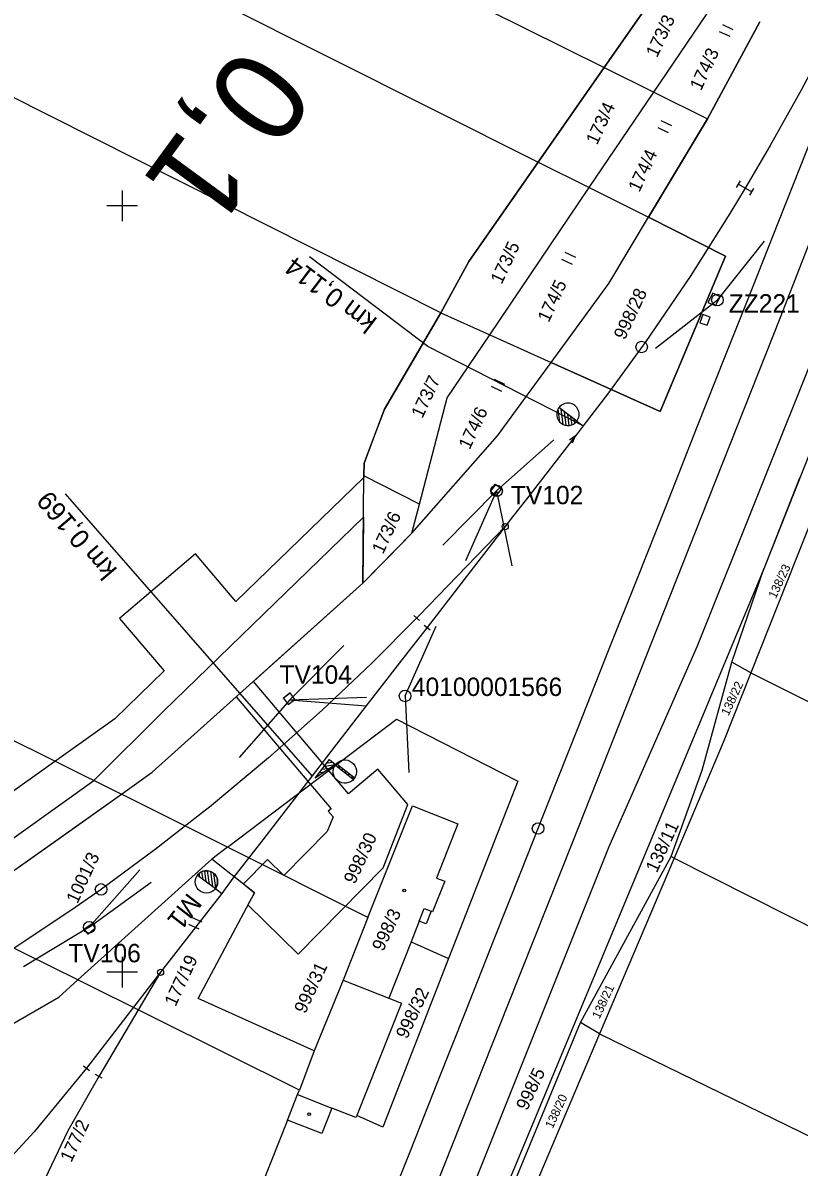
# Model space of a CAD drawing. Extents: x -755344 to -754412, y -1162670 to -1161477.
# Drawn here: x -754912.9 to -754811.6, y -1162225.4 to -1162076.1 of the extents above; entities that cross this region are included whole.
import ezdxf

# ---------------------------------------------------------------- set-up
doc = ezdxf.new("R2010")
doc.units = 0
for name, color, linetype in [('Body ŽBP', 7, 'Continuous'), ('hranice obvodu stavby', 7, 'Continuous'), ('Katastrální hranice', 7, 'Continuous'), ('Staniceni a namezniky', 7, 'Continuous'), ('Síť', 7, 'Continuous'), ('TZ_ostatní', 7, 'Continuous'), ('Vrstva 1', 7, 'Continuous'), ('Vrstva 12', 7, 'Continuous'), ('Vrstva 2', 7, 'Continuous'), ('Vrstva 3', 7, 'Continuous'), ('Vrstva 53', 7, 'Continuous'), ('Vrstva 55', 7, 'Continuous'), ('Vrstva 56', 7, 'Continuous'), ('Vrstva 57', 7, 'Continuous'), ('Vrstva 58', 7, 'Continuous'), ('Vrstva 59', 7, 'Continuous')]:
    doc.layers.add(name, color=color, linetype=linetype)

msp = doc.modelspace()

# ---------------------------------------------------------------- linework, layer by layer
at = {"layer": 'Body ŽBP'}
for p, q in [((-754822.28, -1162112.28), (-754816.13, -1162104.6)), ((-754822.28, -1162112.28), (-754830.36, -1162118.62)), ((-754822.9, -1162111.96), (-754822.9, -1162111.96)), ((-754822.26, -1162112.23), (-754822.3, -1162112.32)), ((-754822.28, -1162112.28), (-754822.28, -1162112.28)), ((-754851.1, -1162137.17), (-754843.64, -1162130.5)), ((-754851.1, -1162137.17), (-754858.13, -1162144.28)), ((-754851.1, -1162137.17), (-754855.18, -1162146.3)), ((-754851.08, -1162137.12), (-754851.12, -1162137.22)), ((-754851.1, -1162137.17), (-754851.1, -1162137.17)), ((-754851.1, -1162137.17), (-754849.12, -1162146.97)), ((-754863.06, -1162163.94), (-754858.98, -1162154.81)), ((-754878.09, -1162164.46), (-754871.05, -1162157.35)), ((-754878.09, -1162164.46), (-754884.71, -1162171.95)), ((-754878.09, -1162164.46), (-754868.09, -1162164.11)), ((-754878.09, -1162164.46), (-754878.09, -1162164.46)), ((-754878.09, -1162164.46), (-754868.11, -1162165.21)), ((-754863.04, -1162163.89), (-754863.08, -1162163.99)), ((-754863.06, -1162163.94), (-754863.06, -1162163.94)), ((-754863.06, -1162163.94), (-754862.54, -1162173.93)), ((-754904.29, -1162194.12), (-754897.67, -1162186.63)), ((-754904.29, -1162194.12), (-754896.22, -1162188.22)), ((-754904.29, -1162194.12), (-754912.85, -1162199.29)), ((-754904.27, -1162194.08), (-754904.31, -1162194.17)), ((-754904.29, -1162194.12), (-754904.29, -1162194.12))]:
    msp.add_line(p, q, dxfattribs=at)
for centre in [(-754822.28, -1162112.28), (-754851.1, -1162137.17), (-754863.06, -1162163.94), (-754904.29, -1162194.12)]:
    msp.add_circle(centre, 0.756, dxfattribs=at)
at = {"layer": 'hranice obvodu stavby'}
for points in [[(-754815.21, -1162048.8), (-754824.54, -1162063.98), (-754828.75, -1162070.02), (-754832.91, -1162075.98), (-754837.06, -1162081.94), (-754845.89, -1162094.59), (-754854.71, -1162107.25), (-754856.54, -1162110.59), (-754858.37, -1162113.93), (-754862.06, -1162120.22), (-754865.75, -1162126.5), (-754867.08, -1162130.03), (-754868.4, -1162133.56), (-754868.42, -1162135.23)], [(-754882.86, -1162162.04), (-754882.32, -1162161.56), (-754868.56, -1162149.23), (-754865.36, -1162145.96), (-754862.16, -1162142.69), (-754850.97, -1162130.01), (-754843.96, -1162120.41), (-754829.74, -1162126.8), (-754821.22, -1162106.53), (-754831.28, -1162101.48), (-754823.58, -1162088.63), (-754816.76, -1162075.96)], [(-754868.42, -1162135.23), (-754868.42, -1162135.42), (-754885.14, -1162151.61), (-754890.41, -1162145.41), (-754900.32, -1162153.82), (-754894.5, -1162160.68), (-754900.94, -1162166.91), (-754920.36, -1162180.69), (-754945.08, -1162194.78), (-754967.54, -1162205.63), (-754992.85, -1162214.58), (-755009.16, -1162219.14), (-755010.64, -1162212), (-755023.37, -1162214.63)], [(-754915.78, -1162187.87), (-754907.92, -1162182.32), (-754900.06, -1162176.77), (-754898.07, -1162175.32), (-754896.07, -1162173.88), (-754885.09, -1162164.04), (-754872.71, -1162178.65), (-754873.09, -1162178.98), (-754872.46, -1162179.71), (-754873.21, -1162181.63), (-754878.88, -1162187.38), (-754881.01, -1162185.28), (-754884.16, -1162188.47), (-754882.73, -1162189.61), (-754883.56, -1162191.19), (-754877.03, -1162197.62), (-754865.92, -1162186.35), (-754862.71, -1162178.08), (-754866.6, -1162173.48), (-754870.42, -1162176.71), (-754882.86, -1162162.04)]]:
    msp.add_lwpolyline(points, dxfattribs=at)
at = {"layer": 'Katastrální hranice'}
msp.add_line((-754811.54, -1162135.54), (-754816.22, -1162147.35), dxfattribs=at)
msp.add_lwpolyline([(-754816.22, -1162147.35), (-754851.45, -1162231.96), (-754887.61, -1162319.28), (-754904.19, -1162359.38)], dxfattribs=at)
at = {"layer": 'Staniceni a namezniky'}
for centre in [(-754832.17, -1162118.4), (-754845.69, -1162181.24), (-754902.74, -1162189.18)]:
    msp.add_circle(centre, 0.75, dxfattribs=at)
at = {"layer": 'Síť'}
for points in [[(-754900, -1162098), (-754900, -1162100), (-754900, -1162102)], [(-754898, -1162100), (-754900, -1162100), (-754902, -1162100)], [(-754900, -1162198), (-754900, -1162200), (-754900, -1162202)], [(-754898, -1162200), (-754900, -1162200), (-754902, -1162200)]]:
    msp.add_lwpolyline(points, dxfattribs=at)
at = {"layer": 'TZ_ostatní'}
msp.add_lwpolyline([(-754923.5, -1162192.2), (-754927.24, -1162190.37), (-754917.66, -1162184.92), (-754903.67, -1162174.98), (-754894.6, -1162165.92), (-754868.47, -1162140.62), (-754868.56, -1162149.23)], dxfattribs=at)
at = {"layer": 'Vrstva 1'}
msp.add_line((-754885.52, -1162187.72), (-754886.99, -1162189.7), dxfattribs=at)
for points in [[(-754814.09, -1162114.62), (-754808.25, -1162099.68), (-754804.47, -1162089.62), (-754798.9, -1162074.23), (-754793.63, -1162059.04), (-754788.99, -1162045.27)], [(-754802.82, -1162068.46), (-754807.01, -1162076.73), (-754811.35, -1162084.87), (-754815.39, -1162092.12), (-754818.66, -1162097.67), (-754820.65, -1162100.99), (-754825.85, -1162109.19), (-754831.64, -1162117.68), (-754836.49, -1162124.37), (-754839.8, -1162128.71), (-754840.46, -1162129.57), (-754840.79, -1162129.99), (-754847.19, -1162138.25), (-754849.01, -1162140.58), (-754849.98, -1162141.84), (-754854.92, -1162148.19), (-754860.18, -1162155.01)], [(-754855.13, -1162205.06), (-754851.41, -1162195.67), (-754847.87, -1162186.72), (-754844.23, -1162177.57), (-754840.47, -1162168.07), (-754836.48, -1162158.01), (-754832.73, -1162148.55), (-754829.03, -1162139.24), (-754824.91, -1162128.83), (-754821.22, -1162119.52), (-754818.37, -1162112.34), (-754814.26, -1162101.97), (-754810.6, -1162092.76), (-754806.3, -1162081.9), (-754802.77, -1162073.01), (-754801.21, -1162069.06)], [(-754832.59, -1162161.33), (-754823.38, -1162138.13), (-754814.09, -1162114.62)], [(-754839.8, -1162128.71), (-754840.46, -1162129.57), (-754840.79, -1162129.99), (-754847.19, -1162138.25), (-754849.01, -1162140.58), (-754849.98, -1162141.84), (-754861.22, -1162153.45), (-754861.54, -1162153.77), (-754867.4, -1162159.65), (-754873.88, -1162165.79), (-754880.89, -1162172.03), (-754888.58, -1162178.44), (-754889.11, -1162178.86), (-754895.68, -1162183.99), (-754902.86, -1162189.27), (-754906.67, -1162191.94), (-754914.99, -1162197.47)], [(-754860.18, -1162155.01), (-754862.55, -1162158.06), (-754867.55, -1162164.48), (-754872.3, -1162170.63), (-754875.17, -1162174.35), (-754879.87, -1162180.43)], [(-754868.98, -1162253.01), (-754858.91, -1162227.64), (-754849.55, -1162204.07), (-754841.17, -1162182.97), (-754832.59, -1162161.33)], [(-754879.87, -1162180.43), (-754881.64, -1162182.7), (-754885.52, -1162187.72)], [(-754886.99, -1162189.7), (-754894.97, -1162200), (-754904.65, -1162212.5)], [(-754886.99, -1162189.7), (-754894.97, -1162200), (-754903.04, -1162213.58)], [(-754873.74, -1162251.98), (-754870.01, -1162242.56), (-754866.47, -1162233.66), (-754862.36, -1162223.3), (-754858.77, -1162214.24), (-754855.13, -1162205.06)], [(-754904.65, -1162212.5), (-754911.48, -1162220.81), (-754920.93, -1162231.04), (-754933.71, -1162243.01), (-754943.62, -1162251.86)], [(-754903.04, -1162213.58), (-754907.06, -1162220.68), (-754913.9, -1162235.02), (-754920.39, -1162251.15)]]:
    msp.add_lwpolyline(points, dxfattribs=at)
at = {"layer": 'Vrstva 12'}
for points in [[(-754823.51, -1162112.58), (-754822.51, -1162112.99), (-754821.93, -1162111.87), (-754822.87, -1162111.37), (-754823.51, -1162112.58)], [(-754824.57, -1162115.27), (-754823.63, -1162115.54), (-754823.22, -1162114.5), (-754824.16, -1162114.18), (-754824.57, -1162115.27)], [(-754851.89, -1162137.21), (-754851.92, -1162137.22), (-754851.27, -1162136.32), (-754851.23, -1162136.34)], [(-754851.16, -1162137.82), (-754850.47, -1162136.96), (-754851.23, -1162136.34), (-754851.89, -1162137.21), (-754851.16, -1162137.82)], [(-754878.92, -1162164.21), (-754878.94, -1162164.18), (-754878.07, -1162163.52), (-754878.04, -1162163.53)], [(-754878.31, -1162165.06), (-754877.46, -1162164.41), (-754878.04, -1162163.53), (-754878.92, -1162164.21), (-754878.31, -1162165.06)], [(-754904.93, -1162194.32), (-754903.92, -1162193.64), (-754903.51, -1162194.27), (-754904.44, -1162195.02), (-754904.93, -1162194.32)]]:
    msp.add_lwpolyline(points, dxfattribs=at)
at = {"layer": 'Vrstva 2'}
for p, q in [((-754840.63, -1162128.08), (-754842.96, -1162126.31)), ((-754842.83, -1162128.23), (-754843.07, -1162126.47)), ((-754842.41, -1162128.52), (-754842.68, -1162126.52)), ((-754842.01, -1162128.64), (-754842.25, -1162126.85)), ((-754841.62, -1162128.64), (-754841.82, -1162127.17)), ((-754841.25, -1162128.55), (-754841.4, -1162127.5)), ((-754840.9, -1162128.34), (-754840.97, -1162127.82)), ((-754840.63, -1162128.08), (-754839.8, -1162128.71)), ((-754861.91, -1162153.43), (-754861.18, -1162154.11)), ((-754860.58, -1162154.7), (-754859.79, -1162155.31)), ((-754890.15, -1162187.32), (-754887.81, -1162189.08)), ((-754889.85, -1162187.55), (-754889.92, -1162187.07)), ((-754889.42, -1162187.87), (-754889.57, -1162186.86)), ((-754889, -1162188.18), (-754889.2, -1162186.75)), ((-754888.58, -1162188.51), (-754888.83, -1162186.75)), ((-754888.15, -1162188.82), (-754888.43, -1162186.85)), ((-754887.75, -1162188.98), (-754888.02, -1162187.1)), ((-754887.81, -1162189.08), (-754886.99, -1162189.7)), ((-754905.04, -1162212.19), (-754904.26, -1162212.82)), ((-754902.6, -1162213.83), (-754903.47, -1162213.34))]:
    msp.add_line(p, q, dxfattribs=at)
for points in [[(-754839.8, -1162128.71), (-754860.1, -1162118.35), (-754875.52, -1162106.64)], [(-754839.8, -1162128.71), (-754840.46, -1162129.57), (-754840.79, -1162129.99), (-754847.19, -1162138.25), (-754849.01, -1162140.58), (-754849.98, -1162141.84), (-754854.92, -1162148.19), (-754860.18, -1162155.01)], [(-754841.19, -1162130.9), (-754840.79, -1162129.99), (-754841.59, -1162130.58)], [(-754849.98, -1162141.84), (-754861.22, -1162153.45), (-754861.54, -1162153.77)], [(-754886.99, -1162189.7), (-754894.97, -1162200), (-754904.65, -1162212.5)], [(-754894.97, -1162200), (-754903.04, -1162213.58)]]:
    msp.add_lwpolyline(points, dxfattribs=at)
for centre, radius in [((-754849.98, -1162141.84), 0.4), ((-754888.98, -1162188.2), 1.46), ((-754894.97, -1162200), 0.4)]:
    msp.add_circle(centre, radius, dxfattribs=at)
for centre, start, end in [((-754841.8, -1162127.19), 142.7915, 322.7523), ((-754841.79, -1162127.19), 322.5371, 143.0066), ((-754888.98, -1162188.2), 323.0119, 142.9728)]:
    msp.add_arc(centre, 1.46, start, end, dxfattribs=at)
at = {"layer": 'Vrstva 3'}
for p, q in [((-754819.77, -1162097.59), (-754819.26, -1162096.73)), ((-754819.52, -1162097.16), (-754817.79, -1162098.17)), ((-754818.05, -1162098.61), (-754817.54, -1162097.74)), ((-754875.17, -1162174.35), (-754907.37, -1162137.56)), ((-754873.23, -1162172.65), (-754872.52, -1162172.56)), ((-754874.21, -1162173.92), (-754873.58, -1162173.85)), ((-754873.89, -1162173.5), (-754872.87, -1162173.38)), ((-754873.56, -1162173.08), (-754872.15, -1162172.9)), ((-754871.86, -1162173.2), (-754871.56, -1162173.17)), ((-754871.43, -1162173.53), (-754871.14, -1162173.5)), ((-754871, -1162173.86), (-754870.71, -1162173.83)), ((-754870.58, -1162174.19), (-754870.29, -1162174.15)), ((-754874.54, -1162174.35), (-754874.28, -1162174.32)), ((-754870.16, -1162174.52), (-754869.87, -1162174.48))]:
    msp.add_line(p, q, dxfattribs=at)
for points in [[(-754874.78, -1162174.65), (-754872.92, -1162172.25), (-754872.12, -1162172.88)], [(-754869.86, -1162174.75), (-754869.73, -1162174.58), (-754871.97, -1162172.85), (-754872.1, -1162173.02)]]:
    msp.add_lwpolyline(points, close=True, dxfattribs=at)
msp.add_ellipse((-754870.92, -1162173.8), major_axis=(-1.2, 0.93), ratio=0.999996, dxfattribs=at)
at = {"layer": 'Vrstva 53'}
for points in [[(-754717.5, -1161955.11), (-754731.42, -1161979.09), (-754747.41, -1161959.83), (-754749.74, -1161970.12), (-754750.32, -1161972.64), (-754745.89, -1161978.47), (-754747.84, -1161978.77), (-754754.27, -1161988.55), (-754756.33, -1161996.85), (-754760.29, -1162004.33), (-754789, -1162076.26), (-754793.13, -1162087.4), (-754798.15, -1162101.07), (-754802.96, -1162113.9), (-754816.22, -1162147.35), (-754851.45, -1162231.96), (-754887.61, -1162319.28)], [(-755014.83, -1162229.55), (-754996.22, -1162224.35), (-754990.29, -1162222.69), (-754980.63, -1162219.28), (-754964.26, -1162213.49), (-754941.12, -1162202.31), (-754923.5, -1162192.2), (-754915.78, -1162187.87), (-754900.06, -1162176.77), (-754896.07, -1162173.88), (-754868.56, -1162149.23), (-754862.16, -1162142.69), (-754861.18, -1162138.93), (-754868.42, -1162135.23), (-754868.4, -1162133.56), (-754865.75, -1162126.5), (-754858.37, -1162113.93), (-754854.71, -1162107.25), (-754837.06, -1162081.94), (-754828.75, -1162070.02)]]:
    msp.add_lwpolyline(points, dxfattribs=at)
at = {"layer": 'Vrstva 55'}
for p, q in [((-754828.75, -1162070.02), (-754837.06, -1162081.94)), ((-754816.76, -1162075.96), (-754823.58, -1162088.63)), ((-754837.06, -1162081.94), (-754845.66, -1162094.27)), ((-754837.06, -1162081.94), (-754830.58, -1162085.16)), ((-754839, -1162097.61), (-754830.58, -1162085.16)), ((-754830.58, -1162085.16), (-754823.58, -1162088.63)), ((-754823.58, -1162088.63), (-754831.28, -1162101.48)), ((-755075.64, -1162089.56), (-754900.06, -1162176.77)), ((-754845.66, -1162094.27), (-754839, -1162097.61)), ((-754851.98, -1162116.8), (-754839, -1162097.61)), ((-754839, -1162097.61), (-754831.28, -1162101.48)), ((-754858.37, -1162113.93), (-754851.98, -1162116.8)), ((-754851.98, -1162116.8), (-754843.96, -1162120.41)), ((-754868.56, -1162149.23), (-754868.42, -1162135.23)), ((-754861.18, -1162138.93), (-754868.42, -1162135.23)), ((-754811.54, -1162135.54), (-754816.22, -1162147.35)), ((-754811.54, -1162135.54), (-754816.22, -1162147.35)), ((-754808.43, -1162137.05), (-754817.91, -1162160.94)), ((-754862.16, -1162142.69), (-754861.18, -1162138.93)), ((-754868.56, -1162149.23), (-754862.16, -1162142.69)), ((-754820.38, -1162159.55), (-754816.22, -1162147.35)), ((-754817.91, -1162160.94), (-754820.38, -1162159.55)), ((-754886.23, -1162183.69), (-754864.19, -1162166.97)), ((-754886.23, -1162183.69), (-754900.06, -1162176.77)), ((-754886.23, -1162183.69), (-754888.26, -1162185.23)), ((-754867.91, -1162192.86), (-754886.23, -1162183.69)), ((-754888.26, -1162185.23), (-754905.78, -1162201)), ((-754840.13, -1162206.56), (-754828.31, -1162184.9)), ((-754827.93, -1162185.11), (-754837.67, -1162208.02)), ((-754827.93, -1162185.11), (-754828.31, -1162184.9)), ((-754905.78, -1162201), (-754923.5, -1162192.2)), ((-754862.27, -1162196.01), (-754857.37, -1162198.21)), ((-754876.85, -1162215.37), (-754905.78, -1162201)), ((-754848.96, -1162227.81), (-754840.13, -1162206.56)), ((-754837.67, -1162208.02), (-754840.13, -1162206.56)), ((-754837.67, -1162208.02), (-754846.58, -1162228.99)), ((-754874.91, -1162210.24), (-754876.85, -1162215.37))]:
    msp.add_line(p, q, dxfattribs=at)
for points in [[(-755057.47, -1161972.1), (-755029.84, -1161984.47), (-754985.77, -1162006.08), (-754934.11, -1162033.82), (-754837.06, -1162081.94)], [(-755060.88, -1161988.66), (-755029.34, -1162001.05), (-755021.14, -1162005.19), (-754997.44, -1162017.02), (-754900.68, -1162066.68), (-754845.66, -1162094.27)], [(-754978.01, -1162551.88), (-754981.37, -1162542.41), (-754930.02, -1162407.36), (-754870.17, -1162267.96), (-754836.4, -1162183.6), (-754824.89, -1162157.4), (-754808.97, -1162117.64), (-754790.52, -1162068.93), (-754761.32, -1161999.17), (-754754.27, -1161988.55)], [(-754858.37, -1162113.93), (-755045.32, -1162019.78), (-755064.79, -1162013.41)], [(-754830.58, -1162085.16), (-754823.72, -1162075.01), (-754822.47, -1162073.13)], [(-754845.66, -1162094.27), (-754854.71, -1162107.25), (-754858.37, -1162113.93)], [(-754843.96, -1162120.41), (-754836.46, -1162110.13), (-754831.28, -1162101.48)], [(-754831.28, -1162101.48), (-754821.22, -1162106.53), (-754829.74, -1162126.8), (-754843.96, -1162120.41)], [(-754868.42, -1162135.23), (-754868.4, -1162133.56), (-754865.75, -1162126.5), (-754858.37, -1162113.93)], [(-754861.18, -1162138.93), (-754857.56, -1162125.05), (-754851.98, -1162116.8)], [(-754862.16, -1162142.69), (-754850.97, -1162130.01), (-754843.96, -1162120.41)], [(-754816.22, -1162147.35), (-754851.45, -1162231.96), (-754887.61, -1162319.28), (-754904.19, -1162359.38)], [(-754816.22, -1162147.35), (-754851.45, -1162231.96), (-754887.61, -1162319.28), (-754904.19, -1162359.38)], [(-754900.06, -1162176.77), (-754896.07, -1162173.88), (-754868.56, -1162149.23)], [(-754828.31, -1162184.9), (-754824.25, -1162173.6), (-754820.38, -1162159.55)], [(-754817.91, -1162160.94), (-754821.51, -1162170), (-754827.93, -1162185.11)], [(-754817.91, -1162160.94), (-754773.06, -1162183.36), (-754661.89, -1162242.23), (-754631.58, -1162259.43)], [(-754864.19, -1162166.97), (-754848.34, -1162175.05), (-754857.37, -1162198.21)], [(-754923.5, -1162192.2), (-754915.78, -1162187.87), (-754900.06, -1162176.77)], [(-754867.91, -1162192.86), (-754862.1, -1162178.26), (-754856.15, -1162180.61), (-754858.96, -1162187.7), (-754857.88, -1162188.11), (-754859.46, -1162192.12), (-754859.66, -1162192.04), (-754860.31, -1162193.68), (-754861.2, -1162193.33), (-754862.27, -1162196.01)], [(-754874.91, -1162210.24), (-754890.05, -1162203.42), (-754882.73, -1162189.61), (-754888.26, -1162185.23)], [(-754827.93, -1162185.11), (-754743.71, -1162227.55), (-754668.64, -1162267.68), (-754640.75, -1162283.26)], [(-754867.91, -1162192.86), (-754871.15, -1162201.02), (-754874.91, -1162210.24)], [(-754862.27, -1162196.01), (-754865.18, -1162203.36), (-754863.54, -1162204.02), (-754869.36, -1162218.68)], [(-754857.37, -1162198.21), (-754865.94, -1162220.19), (-754869.36, -1162218.68)], [(-754971.15, -1162234.1), (-754958.95, -1162230.19), (-754951.07, -1162227.67), (-754947.14, -1162225.65), (-754943.74, -1162223.69), (-754908.27, -1162203.24), (-754905.78, -1162201)], [(-754837.67, -1162208.02), (-754737.97, -1162256.6), (-754682.13, -1162286.58), (-754649.24, -1162305.33)], [(-754878.41, -1162219.27), (-754877.09, -1162215.93), (-754876.85, -1162215.37)], [(-754869.36, -1162218.68), (-754869.47, -1162218.96), (-754872.61, -1162217.71), (-754873.93, -1162221.05), (-754878.41, -1162219.27)], [(-754878.41, -1162219.27), (-754890.63, -1162250.1), (-754895.21, -1162261.65), (-754899.8, -1162273.21), (-754904.37, -1162284.73), (-754908.92, -1162296.21), (-754913.49, -1162307.74), (-754920.81, -1162326.21)]]:
    msp.add_lwpolyline(points, dxfattribs=at)
at = {"layer": 'Vrstva 56'}
for p, q in [((-754861.2, -1162193.33), (-754860.55, -1162191.69)), ((-754860.55, -1162191.69), (-754859.66, -1162192.04)), ((-754871.15, -1162201.02), (-754865.18, -1162203.36)), ((-754877.09, -1162215.93), (-754872.61, -1162217.71))]:
    msp.add_line(p, q, dxfattribs=at)
at = {"layer": 'Vrstva 58'}
for p, q in [((-754820.2, -1162077), (-754821.56, -1162076.36)), ((-754820.63, -1162077.9), (-754821.99, -1162077.27)), ((-754828.24, -1162089.53), (-754829.6, -1162088.9)), ((-754828.66, -1162090.44), (-754830.02, -1162089.8)), ((-754841.21, -1162107.62), (-754842.57, -1162106.99)), ((-754840.78, -1162106.72), (-754842.14, -1162106.08)), ((-754850.01, -1162123.29), (-754851.37, -1162122.66)), ((-754850.43, -1162124.2), (-754851.79, -1162123.57)), ((-754889.52, -1162193.47), (-754890.88, -1162192.84)), ((-754889.95, -1162194.38), (-754891.3, -1162193.74))]:
    msp.add_line(p, q, dxfattribs=at)
at = {"layer": 'Vrstva 59'}
for centre in [(-754863.16, -1162189.31), (-754875.58, -1162218.5)]:
    msp.add_circle(centre, 0.175, dxfattribs=at)

# ---------------------------------------------------------------- texts
at = {"layer": 'Body ŽBP'}
for s, p in [(' ZZ221', (-754821.69, -1162113.91)), (' TV102', (-754850.13, -1162138.92)), (' TV104', (-754880.34, -1162162.34)), (' 40100001566', (-754863.06, -1162163.94)), (' TV106', (-754907.9, -1162198.69))]:
    msp.add_text(s, height=2.4, dxfattribs=at).set_placement(p)
at = {"layer": 'Staniceni a namezniky'}
msp.add_text('0,1', height=12, rotation=233.7782, dxfattribs=at).set_placement((-754884.25, -1162078.64))
at = {"layer": 'Vrstva 2'}
for s, rotation, p in [('km 0,114', 142.7719, (-754866.54, -1162114.78)), ('M1', 232.2531, (-754891.4, -1162189.49))]:
    msp.add_text(s, height=2.5, rotation=rotation, dxfattribs=at).set_placement(p)
at = {"layer": 'Vrstva 3'}
msp.add_text('km 0,169', height=2.5, rotation=130.2896, dxfattribs=at).set_placement((-754900.52, -1162147.45))
at = {"layer": 'Vrstva 57'}
for s, height, p in [('173/3', 1.7, (-754830.16, -1162080.73)), ('174/3', 1.7, (-754824.42, -1162085.06)), ('173/4', 1.7, (-754837.99, -1162092.13)), ('174/4', 1.7, (-754832.47, -1162098.3)), ('173/5', 1.7, (-754850.44, -1162110.31)), ('174/5', 1.7, (-754844.3, -1162115.3)), ('998/28', 1.7, (-754834.36, -1162117.56)), ('173/7', 1.7, (-754860.8, -1162127.81)), ('174/6', 1.7, (-754854.62, -1162131.89)), ('173/6', 1.7, (-754865.93, -1162145.53)), ('138/23', 1.139, (-754814.66, -1162151.31)), ('138/22', 1.139, (-754820.83, -1162166.6)), ('138/11', 1.7, (-754830.19, -1162187.1)), ('998/30', 1.7, (-754869.61, -1162188.59)), ('1001/3', 1.7, (-754905.83, -1162191.15)), ('998/3', 1.7, (-754865.92, -1162197.37)), ('177/19', 1.7, (-754893.02, -1162204.56)), ('998/31', 1.7, (-754876.08, -1162205.5)), ('998/32', 1.7, (-754862.8, -1162208.8)), ('138/21', 1.139, (-754837.68, -1162206.16)), ('998/5', 1.7, (-754847.11, -1162218.14)), ('138/20', 1.139, (-754843.79, -1162220.47)), ('177/2', 1.7, (-754906.63, -1162224.9))]:
    msp.add_text(s, height=height, rotation=65, dxfattribs=at).set_placement(p)

doc.saveas('drawing.dxf')
